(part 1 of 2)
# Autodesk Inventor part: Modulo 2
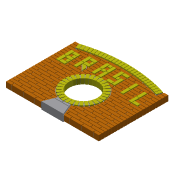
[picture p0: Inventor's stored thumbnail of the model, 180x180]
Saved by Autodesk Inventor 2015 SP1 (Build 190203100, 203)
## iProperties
Created: 2015-04
Part Number: Modulo 2
Material: Generic
Document SubType Name: Modeling
Designer: treina2
Density: 1 g/cm^3
Appearance: Default
Author: treina2
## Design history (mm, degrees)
sketch "Sketch1"
  geometry: L1 (740, 1360)-(740, 1418) reference; L2 (954, 1088)-(954, 1146) reference; L3 (740, 1088)-(740, 1146) reference; L4 (740, 1292)-(740, 1350) reference; L5 (954, 1224)-(954, 1282) reference; L6 (954, 1360)-(954, 1418) reference; L7 (954, 1292)-(954, 1350) reference; L8 (954, 1156)-(954, 1214) reference; L9 (740, 1156)-(740, 1214) reference; L10 (740, 1224)-(740, 1282) reference; L11 (1990, 534)-(1990, 544) reference; L12 (1990, 1350)-(1990, 1360) reference; L13 (740, 262)-(500, 262) reference; L14 (500, 262)-(500, 204) reference; L15 (1875, 136)-(1990, 136) reference; L16 (1990, 136)-(1990, 194) reference; L17 (1990, 194)-(1875, 194) reference; L18 (1875, 194)-(1875, 136) reference; L19 (250, 68)-(490, 68) reference; L20 (490, 68)-(490, 126) reference; L21 (490, 126)-(250, 126) reference; L22 (250, 126)-(250, 68) reference; L23 (750, 68)-(777.045, 68) reference; L24 (1250, 204)-(1490, 204) reference; L25 (1490, 204)-(1490, 262) reference; L26 (1490, 262)-(1250, 262) reference; L27 (1250, 262)-(1250, 204) reference; L28 (1500, 204)-(1740, 204) reference; L29 (1740, 204)-(1740, 262) reference; L30 (1740, 262)-(1500, 262) reference; L31 (1500, 262)-(1500, 204) reference; L32 (125, 136)-(365, 136) reference; L33 (365, 136)-(365, 194) reference; L34 (365, 194)-(125, 194) reference; L35 (125, 194)-(125, 136) reference; L36 (0, 476)-(240, 476) reference; L37 (240, 476)-(240, 534) reference; L38 (240, 534)-(0, 534) reference; L39 (0, 534)-(0, 476) reference; L40 (115, 408)-(0, 408) reference; L41 (0, 408)-(0, 466) reference; L42 (0, 466)-(115, 466) reference; L43 (115, 466)-(115, 408) reference; L44 (1750, 1020)-(1990, 1020) reference; L45 (1990, 1020)-(1990, 1078) reference; L46 (1990, 1078)-(1750, 1078) reference; L47 (1750, 1078)-(1750, 1020) reference; L48 (375, 680)-(570.34, 680) reference; L49 (1500, 884)-(1740, 884) reference; L50 (1740, 884)-(1740, 942) reference; L51 (1740, 942)-(1500, 942) reference; L52 (1500, 942)-(1500, 884) reference; L53 (1750, 884)-(1990, 884) reference; L54 (1990, 884)-(1990, 942) reference; L55 (1990, 942)-(1750, 942) reference; L56 (1750, 942)-(1750, 884) reference; L57 (1250, 1292)-(1422, 1292) reference; L58 (750, 1020)-(764.401, 1020) reference; L59 (250, 1214)-(250, 1156) reference; L60 (250, 1156)-(308, 1156) reference; L61 (750, 1258)-(750, 1418) reference; L62 (750, 1418)-(808, 1418) reference; L63 (808, 1418)-(808, 1258) reference; L64 (808, 1258)-(750, 1258) reference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; C1 r 300 at (995, 663) reference; C2 r 300 at (995, 663) reference; C3 r 300 at (995, 663) reference; C4 r 300 at (995, 663) reference; C5 r 300 at (995, 663) reference; C6 r 300 at (995, 663) reference; A1 r 425 centre (995, 663) between (749.611, 1010) and (683.385, 952) reference; A2 r 2840.721 centre (995, -1354.721) between (490, 1440.752) and (423.896, 1428) reference; A3 r 425 centre (995, 663) between (1411.413, 748) and (1395.22, 806) reference; A4 r 425 centre (995, 663) between (1419.66, 680) and (1413.33, 738) reference; A5 r 425 centre (995, 663) between (863.689, 258.794) and (990, 238.029) reference; A6 r 425 centre (995, 663) between (594.78, 806) and (578.587, 748) reference; A7 r 2840.721 centre (995, -1354.721) between (1615, 1417.516) and (1612.83, 1418) reference; A8 r 425 centre (995, 663) between (903.348, 1078) and (764.401, 1020) reference; A9 r 425 centre (995, 663) between (1376.649, 476) and (1399.949, 534) reference; A10 r 425 centre (995, 663) between (662.735, 398) and (718.783, 340) reference; A11 r 425 centre (995, 663) between (1358.021, 884) and (1315.599, 942) reference; A12 r 425 centre (995, 663) between (1365, 872.105) and (1363.923, 874) reference; A13 r 425 centre (995, 663) between (1225.599, 1020) and (1086.652, 1078) reference; A14 r 425 centre (995, 663) between (1403, 544) and (1415.6, 602) reference; A15 r 425 centre (995, 663) between (1416.929, 612) and (1419.942, 670) reference; A16 r 425 centre (995, 663) between (1161.565, 272) and (1259.076, 330) reference; A17 r 425 centre (995, 663) between (1271.217, 340) and (1327.265, 398) reference; A18 r 425 centre (995, 663) between (1335, 408) and (1365, 453.895) reference; A19 r 425 centre (995, 663) between (574.4, 602) and (587, 544) reference; A20 r 425 centre (995, 663) between (590.051, 534) and (613.351, 476) reference; A21 r 425 centre (995, 663) between (1000, 238.029) and (1126.311, 258.794) reference; A22 r 425 centre (995, 663) between (576.67, 738) and (570.34, 680) reference; A23 r 425 centre (995, 663) between (730.924, 330) and (828.435, 272) reference; A24 r 425 centre (995, 663) between (615, 853.329) and (598.495, 816) reference; A25 r 425 centre (995, 663) between (626.077, 874) and (625, 872.105) reference; A26 r 2840.721 centre (995, -1354.721) between (1831.651, 1360) and (1625, 1415.26) reference; A27 r 425 centre (995, 663) between (674.401, 942) and (631.979, 884) reference; A28 r 2840.721 centre (995, -1354.721) between (365, 1415.26) and (158.349, 1360) reference; A29 r 2840.721 centre (995, -1354.721) between (990, 1485.996) and (750, 1475.415) reference; A30 r 2840.721 centre (995, -1354.721) between (740, 1474.532) and (500, 1442.54) reference; A31 r 2840.721 centre (995, -1354.721) between (377.17, 1418) and (375, 1417.516) reference; A32 r 425 centre (995, 663) between (570.058, 670) and (573.071, 612) reference; A33 r 425 centre (995, 663) between (1391.505, 816) and (1375, 853.329) reference; A34 r 425 centre (995, 663) between (625, 453.895) and (655, 408) reference; A35 r 425 centre (995, 663) between (1306.615, 952) and (1240.389, 1010) reference; A36 r 2840.721 centre (995, -1354.721) between (1490, 1442.54) and (1250, 1474.532) reference; A37 r 2840.721 centre (995, -1354.721) between (1240, 1475.415) and (1000, 1485.996) reference; A38 r 2840.721 centre (995, -1354.721) between (1566.104, 1428) and (1500, 1440.752) reference; 1 further point
  constraints: 2472 end point, 508 horizontal, 481 vertical, 127 point on line, 76 point on circle, 44 centre point, 1 midpoint, 1471 other
extrude "Extrusion1" new body sketch "Sketch1" distance "d0" = 115 (= T_P_L); taper "d1" = 0 deg
extrude "Extrusion2" new body sketch "Sketch1" distance "d2" = 115 (= T_P_L); taper "d3" = 0 deg
extrude "Extrusion3" new body sketch "Sketch1" distance "d4" = 115 (= T_P_L); taper "d5" = 0 deg
extrude "Extrusion4" new body sketch "Sketch1" distance "d6" = 115 (= T_P_L); taper "d7" = 0 deg
extrude "Extrusion6" new body sketch "Sketch1" distance "d10" = 115 (= T_P_L); taper "d11" = 0 deg
extrude "Extrusion7" new body sketch "Sketch1" distance "d12" = 115 (= T_P_L); taper "d13" = 0 deg
extrude "Extrusion8" new body sketch "Sketch1" distance "d14" = 115 (= T_P_L); taper "d15" = 0 deg
extrude "Extrusion9" new body sketch "Sketch1" distance "d16" = 115 (= T_P_L); taper "d17" = 0 deg
extrude "Extrusion10" new body sketch "Sketch1" distance "d18" = 115 (= T_P_L); taper "d19" = 0 deg
extrude "Extrusion11" new body sketch "Sketch1" distance "d20" = 115 (= T_P_L); taper "d21" = 0 deg
extrude "Extrusion12" new body sketch "Sketch1" distance "d22" = 115 (= T_P_L); taper "d23" = 0 deg
extrude "Extrusion13" new body sketch "Sketch1" distance "d24" = 115 (= T_P_L); taper "d25" = 0 deg
extrude "Extrusion14" new body sketch "Sketch1" distance "d26" = 115 (= T_P_L); taper "d27" = 0 deg
extrude "Extrusion15" new body sketch "Sketch1" distance "d28" = 115 (= T_P_L); taper "d29" = 0 deg
pattern_linear "Rectangular Pattern1" dims "d32" = 136 (= 2 x T_P_P + 2 x GAP)
pattern_linear "Rectangular Pattern2" dims "d35" = 136 (= 2 x T_P_P + 2 x GAP)
pattern_linear "Rectangular Pattern3" dims "d38" = 136 (= 2 x T_P_P + 2 x GAP)
pattern_linear "Rectangular Pattern4" dims "d41" = 136 (= 2 x T_P_P + 2 x GAP)
pattern_linear "Rectangular Pattern5" dims "d44" = 136 (= 2 x T_P_P + 2 x GAP)
pattern_linear "Rectangular Pattern6" dims "d47" = 136 (= 2 x T_P_P + 2 x GAP)
extrude "Extrusion16" new body sketch "Sketch1" distance "d48" = 115 (= T_P_L); taper "d49" = 0 deg
extrude "Extrusion17" new body sketch "Sketch1" distance "d50" = 115 (= T_P_L); taper "d51" = 0 deg
extrude "Extrusion18" new body sketch "Sketch1" distance "d52" = 115 (= T_P_L); taper "d53" = 0 deg
pattern_linear "Rectangular Pattern7" dims "d56" = 136 (= 2 x T_P_P + 2 x GAP)
pattern_linear "Rectangular Pattern8" dims "d59" = 136 (= 2 x T_P_P + 2 x GAP)
pattern_linear "Rectangular Pattern9" dims "d62" = 136 (= 2 x T_P_P + 2 x GAP)
pattern_linear "Rectangular Pattern10" dims "d65" = 136 (= 2 x T_P_P + 2 x GAP)
pattern_linear "Rectangular Pattern11" dims "d68" = 136 (= 2 x T_P_P + 2 x GAP)
extrude "Extrusion19" new body sketch "Sketch1" distance "d69" = 115 (= T_P_L); taper "d70" = 0 deg
extrude "Extrusion20" new body sketch "Sketch1" distance "d71" = 115 (= T_P_L); taper "d72" = 0 deg
extrude "Extrusion21" new body sketch "Sketch1" distance "d73" = 115 (= T_P_L); taper "d74" = 0 deg
extrude "Extrusion22" new body sketch "Sketch1" distance "d75" = 115 (= T_P_L); taper "d76" = 0 deg
extrude "Extrusion25" new body sketch "Sketch1" distance "d81" = 115 (= T_P_L); taper "d82" = 0 deg
extrude "Extrusion26" new body sketch "Sketch1" distance "d83" = 115 (= T_P_L); taper "d84" = 0 deg
extrude "Extrusion27" new body sketch "Sketch1" distance "d85" = 115 (= T_P_L); taper "d86" = 0 deg
extrude "Extrusion28" new body sketch "Sketch1" distance "d87" = 115 (= T_P_L); taper "d88" = 0 deg
extrude "Extrusion29" new body sketch "Sketch1" distance "d89" = 115 (= T_P_L); taper "d90" = 0 deg
extrude "Extrusion30" new body sketch "Sketch1" distance "d91" = 115 (= T_P_L); taper "d92" = 0 deg
extrude "Extrusion31" new body sketch "Sketch1" distance "d93" = 115 (= T_P_L); taper "d94" = 0 deg
extrude "Extrusion32" new body sketch "Sketch1" distance "d95" = 115 (= T_P_L); taper "d96" = 0 deg
extrude "Extrusion33" new body sketch "Sketch1" distance "d97" = 115 (= T_P_L); taper "d98" = 0 deg
extrude "Extrusion34" new body sketch "Sketch1" distance "d99" = 115 (= T_P_L); taper "d100" = 0 deg
extrude "Extrusion35" new body sketch "Sketch1" distance "d101" = 115 (= T_P_L); taper "d102" = 0 deg
extrude "Extrusion36" new body sketch "Sketch1" distance "d103" = 115 (= T_P_L); taper "d104" = 0 deg
extrude "Extrusion37" new body sketch "Sketch1" distance "d105" = 115 (= T_P_L); taper "d106" = 0 deg
extrude "Extrusion38" new body sketch "Sketch1" distance "d107" = 115 (= T_P_L); taper "d108" = 0 deg
extrude "Extrusion39" new body sketch "Sketch1" distance "d109" = 115 (= T_P_L); taper "d110" = 0 deg
extrude "Extrusion40" new body sketch "Sketch1" distance "d111" = 115 (= T_P_L); taper "d112" = 0 deg
extrude "Extrusion41" new body sketch "Sketch1" distance "d113" = 115 (= T_P_L); taper "d114" = 0 deg
extrude "Extrusion42" new body sketch "Sketch1" distance "d115" = 115 (= T_P_L); taper "d116" = 0 deg
extrude "Extrusion43" new body sketch "Sketch1" distance "d117" = 115 (= T_P_L); taper "d118" = 0 deg
extrude "Extrusion44" new body sketch "Sketch1" distance "d119" = 115 (= T_P_L); taper "d120" = 0 deg
extrude "Extrusion45" new body sketch "Sketch1" distance "d121" = 115 (= T_P_L); taper "d122" = 0 deg
extrude "Extrusion46" new body sketch "Sketch1" distance "d123" = 115 (= T_P_L); taper "d124" = 0 deg
extrude "Extrusion47" new body sketch "Sketch1" distance "d125" = 115 (= T_P_L); taper "d126" = 0 deg
extrude "Extrusion48" new body sketch "Sketch1" distance "d127" = 115 (= T_P_L); taper "d128" = 0 deg
extrude "Extrusion49" new body sketch "Sketch1" distance "d129" = 115 (= T_P_L); taper "d130" = 0 deg
extrude "Extrusion50" new body sketch "Sketch1" distance "d131" = 115 (= T_P_L); taper "d132" = 0 deg
extrude "Extrusion51" new body sketch "Sketch1" distance "d133" = 115 (= T_P_L); taper "d134" = 0 deg
extrude "Extrusion52" new body sketch "Sketch1" distance "d135" = 115 (= T_P_L); taper "d136" = 0 deg
extrude "Extrusion53" new body sketch "Sketch1" distance "d137" = 115 (= T_P_L); taper "d138" = 0 deg
pattern_linear "Rectangular Pattern12" dims "d141" = 136 (= 2 x T_P_P + 2 x GAP)
pattern_linear "Rectangular Pattern13" dims "d144" = 136 (= 2 x T_P_P + 2 x GAP)
extrude "Extrusion54" new body sketch "Sketch1" distance "d145" = 115 (= T_P_L); taper "d146" = 0 deg
extrude "Extrusion55" new body sketch "Sketch1" distance "d147" = 115 (= T_P_L); taper "d148" = 0 deg
extrude "Extrusion56" new body sketch "Sketch1" distance "d149" = 115 (= T_P_L); taper "d150" = 0 deg
extrude "Extrusion57" new body sketch "Sketch1" distance "d151" = 115 (= T_P_L); taper "d152" = 0 deg
extrude "Extrusion58" new body sketch "Sketch1" distance "d153" = 115 (= T_P_L); taper "d154" = 0 deg
extrude "Extrusion59" new body sketch "Sketch1" distance "d155" = 115 (= T_P_L); taper "d156" = 0 deg
extrude "Extrusion60" new body sketch "Sketch1" distance "d157" = 115 (= T_P_L); taper "d158" = 0 deg
extrude "Extrusion61" new body sketch "Sketch1" distance "d159" = 115 (= T_P_L); taper "d160" = 0 deg
extrude "Extrusion62" new body sketch "Sketch1" distance "d161" = 115 (= T_P_L); taper "d162" = 0 deg
pattern_linear "Rectangular Pattern14" dims "d165" = 68 (= T_P_P + GAP)
extrude "Extrusion63" new body sketch "Sketch1" distance "d166" = 115 (= T_P_L); taper "d167" = 0 deg
extrude "Extrusion64" new body sketch "Sketch1" distance "d168" = 115 (= T_P_L); taper "d169" = 0 deg
extrude "Extrusion65" new body sketch "Sketch1" distance "d170" = 115 (= T_P_L); taper "d171" = 0 deg
extrude "Extrusion66" new body sketch "Sketch1" distance "d172" = 115 (= T_P_L); taper "d173" = 0 deg
extrude "Extrusion67" new body sketch "Sketch1" distance "d174" = 115 (= T_P_L); taper "d175" = 0 deg
extrude "Extrusion68" new body sketch "Sketch1" distance "d176" = 115 (= T_P_L); taper "d177" = 0 deg
extrude "Extrusion69" new body sketch "Sketch1" distance "d178" = 115 (= T_P_L); taper "d179" = 0 deg
extrude "Extrusion70" new body sketch "Sketch1" distance "d180" = 115 (= T_P_L); taper "d181" = 0 deg
pattern_linear "Rectangular Pattern15" dims "d184" = 68 (= T_P_P + GAP)
extrude "Extrusion71" new body sketch "Sketch1" distance "d185" = 115 (= T_P_L); taper "d186" = 0 deg
extrude "Extrusion72" new body sketch "Sketch1" distance "d187" = 115 (= T_P_L); taper "d188" = 0 deg
extrude "Extrusion73" new body sketch "Sketch1" distance "d189" = 115 (= T_P_L); taper "d190" = 0 deg
extrude "Extrusion74" new body sketch "Sketch1" distance "d191" = 115 (= T_P_L); taper "d192" = 0 deg
extrude "Extrusion75" new body sketch "Sketch1" distance "d193" = 115 (= T_P_L); taper "d194" = 0 deg
extrude "Extrusion76" new body sketch "Sketch1" distance "d195" = 115 (= T_P_L); taper "d196" = 0 deg
extrude "Extrusion77" new body sketch "Sketch1" distance "d197" = 115 (= T_P_L); taper "d198" = 0 deg
extrude "Extrusion78" new body sketch "Sketch1" distance "d199" = 115 (= T_P_L); taper "d200" = 0 deg
extrude "Extrusion79" new body sketch "Sketch1" distance "d201" = 115 (= T_P_L); taper "d202" = 0 deg
extrude "Extrusion80" new body sketch "Sketch1" distance "d203" = 115 (= T_P_L); taper "d204" = 0 deg
extrude "Extrusion81" new body sketch "Sketch1" distance "d205" = 115 (= T_P_L); taper "d206" = 0 deg
extrude "Extrusion82" new body sketch "Sketch1" distance "d207" = 115 (= T_P_L); taper "d208" = 0 deg
extrude "Extrusion83" new body sketch "Sketch1" distance "d209" = 115 (= T_P_L); taper "d210" = 0 deg
extrude "Extrusion84" new body sketch "Sketch1" distance "d211" = 115 (= T_P_L); taper "d212" = 0 deg
extrude "Extrusion85" new body sketch "Sketch1" distance "d213" = 115 (= T_P_L); taper "d214" = 0 deg
extrude "Extrusion86" new body sketch "Sketch1" distance "d215" = 115 (= T_P_L); taper "d216" = 0 deg
extrude "Extrusion87" new body sketch "Sketch1" distance "d217" = 115 (= T_P_L); taper "d218" = 0 deg
extrude "Extrusion88" new body sketch "Sketch1" distance "d219" = 115 (= T_P_L); taper "d220" = 0 deg
extrude "Extrusion89" new body sketch "Sketch1" distance "d221" = 115 (= T_P_L); taper "d222" = 0 deg
extrude "Extrusion90" new body sketch "Sketch1" distance "d223" = 115 (= T_P_L); taper "d224" = 0 deg
extrude "Extrusion91" new body sketch "Sketch1" distance "d225" = 115 (= T_P_L); taper "d226" = 0 deg
extrude "Extrusion92" new body sketch "Sketch1" distance "d227" = 115 (= T_P_L); taper "d228" = 0 deg
extrude "Extrusion93" new body sketch "Sketch1" distance "d229" = 115 (= T_P_L); taper "d230" = 0 deg
extrude "Extrusion94" new body sketch "Sketch1" distance "d231" = 115 (= T_P_L); taper "d232" = 0 deg
extrude "Extrusion95" new body sketch "Sketch1" distance "d233" = 115 (= T_P_L); taper "d234" = 0 deg
extrude "Extrusion96" new body sketch "Sketch1" distance "d235" = 115 (= T_P_L); taper "d236" = 0 deg
extrude "Extrusion97" new body sketch "Sketch1" distance "d237" = 115 (= T_P_L); taper "d238" = 0 deg
extrude "Extrusion98" new body sketch "Sketch1" distance "d239" = 115 (= T_P_L); taper "d240" = 0 deg
extrude "Extrusion99" new body sketch "Sketch1" distance "d241" = 115 (= T_P_L); taper "d242" = 0 deg
extrude "Extrusion100" new body sketch "Sketch1" distance "d243" = 115 (= T_P_L); taper "d244" = 0 deg
extrude "Extrusion101" new body sketch "Sketch1" distance "d245" = 115 (= T_P_L); taper "d246" = 0 deg
extrude "Extrusion102" new body sketch "Sketch1" distance "d247" = 115 (= T_P_L); taper "d248" = 0 deg
extrude "Extrusion103" new body sketch "Sketch1" distance "d249" = 115 (= T_P_L); taper "d250" = 0 deg
extrude "Extrusion104" new body sketch "Sketch1" distance "d251" = 115 (= T_P_L); taper "d252" = 0 deg
extrude "Extrusion105" new body sketch "Sketch1" distance "d253" = 115 (= T_P_L); taper "d254" = 0 deg
workplane "Work Plane1"
sketch "Sketch2"
  geometry: L1 (0, 1292)-(0, 1350); L2 (214, 1020)-(214, 1078); L3 (0, 1020)-(0, 1078); L4 (0, 1224)-(0, 1282); L5 (214, 1156)-(214, 1214); L6 (214, 1292)-(214, 1350); L7 (214, 1224)-(214, 1282); L8 (214, 1088)-(214, 1146); L9 (0, 1088)-(0, 1146); L10 (0, 1156)-(0, 1214); L11 (1250, 466)-(1250, 476); L12 (1250, 1282)-(1250, 1292); L13 (0, 194)-(-240, 194); L14 (-240, 194)-(-240, 136); L15 (1135, 68)-(1250, 68); L16 (1250, 68)-(1250, 126); L17 (1250, 126)-(1135, 126); L18 (1135, 126)-(1135, 68); L19 (-490, 0)-(-250, 0); L20 (-250, 0)-(-250, 58); L21 (-250, 58)-(-490, 58); L22 (-490, 58)-(-490, 0); L23 (10, 0)-(37.045, 0); L24 (510, 136)-(750, 136); L25 (750, 136)-(750, 194); L26 (750, 194)-(510, 194); L27 (510, 194)-(510, 136); L28 (760, 136)-(1000, 136); L29 (1000, 136)-(1000, 194); L30 (1000, 194)-(760, 194); L31 (760, 194)-(760, 136); L32 (-615, 68)-(-375, 68); L33 (-375, 68)-(-375, 126); L34 (-375, 126)-(-615, 126); L35 (-615, 126)-(-615, 68); L36 (-740, 408)-(-500, 408); L37 (-500, 408)-(-500, 466); L38 (-500, 466)-(-740, 466); L39 (-740, 466)-(-740, 408); L40 (-625, 340)-(-740, 340); L41 (-740, 340)-(-740, 398); L42 (-740, 398)-(-625, 398); L43 (-625, 398)-(-625, 340); L44 (1010, 952)-(1250, 952); L45 (1250, 952)-(1250, 1010); L46 (1250, 1010)-(1010, 1010); L47 (1010, 1010)-(1010, 952); L48 (-365, 612)-(-169.66, 612); L49 (760, 816)-(1000, 816); L50 (1000, 816)-(1000, 874); L51 (1000, 874)-(760, 874); L52 (760, 874)-(760, 816); L53 (1010, 816)-(1250, 816); L54 (1250, 816)-(1250, 874); L55 (1250, 874)-(1010, 874); L56 (1010, 874)-(1010, 816); L57 (510, 1224)-(682, 1224); L58 (10, 952)-(24.401, 952); L59 (-490, 1146)-(-490, 1088); L60 (-490, 1088)-(-432, 1088); L61 (10, 1190)-(10, 1350); L62 (10, 1350)-(68, 1350); L63 (68, 1350)-(68, 1190); L64 (68, 1190)-(10, 1190)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; C1 r 300 at (255, 595); C2 r 300 at (255, 595); C3 r 300 at (255, 595); C4 r 300 at (255, 595); C5 r 300 at (255, 595); C6 r 300 at (255, 595); A1 r 425 centre (255, 595) between (9.611, 942) and (-56.615, 884); A2 r 2840.721 centre (255, -1422.721) between (-250, 1372.752) and (-316.104, 1360); A3 r 425 centre (255, 595) between (671.413, 680) and (655.22, 738); A4 r 425 centre (255, 595) between (679.66, 612) and (673.33, 670); A5 r 425 centre (255, 595) between (123.689, 190.794) and (250, 170.029); A6 r 425 centre (255, 595) between (-145.22, 738) and (-161.413, 680); A7 r 2840.721 centre (255, -1422.721) between (875, 1349.516) and (872.83, 1350); A8 r 425 centre (255, 595) between (163.348, 1010) and (24.401, 952); A9 r 425 centre (255, 595) between (636.649, 408) and (659.949, 466); A10 r 425 centre (255, 595) between (-77.265, 330) and (-21.217, 272); A11 r 425 centre (255, 595) between (618.021, 816) and (575.599, 874); A12 r 425 centre (255, 595) between (625, 804.105) and (623.923, 806); A13 r 425 centre (255, 595) between (485.599, 952) and (346.652, 1010); A14 r 425 centre (255, 595) between (663, 476) and (675.6, 534); A15 r 425 centre (255, 595) between (676.929, 544) and (679.942, 602); A16 r 425 centre (255, 595) between (421.565, 204) and (519.076, 262); A17 r 425 centre (255, 595) between (531.217, 272) and (587.265, 330); A18 r 425 centre (255, 595) between (595, 340) and (625, 385.895); A19 r 425 centre (255, 595) between (-165.6, 534) and (-153, 476); A20 r 425 centre (255, 595) between (-149.949, 466) and (-126.649, 408); A21 r 425 centre (255, 595) between (260, 170.029) and (386.311, 190.794); A22 r 425 centre (255, 595) between (-163.33, 670) and (-169.66, 612); A23 r 425 centre (255, 595) between (-9.076, 262) and (88.435, 204); A24 r 425 centre (255, 595) between (-125, 785.329) and (-141.505, 748); A25 r 425 centre (255, 595) between (-113.923, 806) and (-115, 804.105); A26 r 2840.721 centre (255, -1422.721) between (1091.651, 1292) and (885, 1347.26); A27 r 425 centre (255, 595) between (-65.599, 874) and (-108.021, 816); A28 r 2840.721 centre (255, -1422.721) between (-375, 1347.26) and (-581.651, 1292); A29 r 2840.721 centre (255, -1422.721) between (250, 1417.996) and (10, 1407.415); A30 r 2840.721 centre (255, -1422.721) between (0, 1406.532) and (-240, 1374.54); A31 r 2840.721 centre (255, -1422.721) between (-362.83, 1350) and (-365, 1349.516); A32 r 425 centre (255, 595) between (-169.942, 602) and (-166.929, 544); A33 r 425 centre (255, 595) between (651.505, 748) and (635, 785.329); A34 r 425 centre (255, 595) between (-115, 385.895) and (-85, 340); A35 r 425 centre (255, 595) between (566.615, 884) and (500.389, 942); A36 r 2840.721 centre (255, -1422.721) between (750, 1374.54) and (510, 1406.532); A37 r 2840.721 centre (255, -1422.721) between (500, 1407.415) and (260, 1417.996); A38 r 2840.721 centre (255, -1422.721) between (826.104, 1360) and (760, 1372.752); 2 further points
  constraints: 2472 end point, 127 point on line, 76 point on circle, 44 centre point, 1 midpoint
extrude "Extrusion106" new body sketch "Sketch2" distance "d255" = 15; taper "d257" = 0 deg; dims "d256" = 140 (derived), "d258" = 0
extrude "Extrusion107" new body sketch "Sketch2" distance "d259" = 15; taper "d261" = 0 deg; dims "d260" = 140 (derived), "d262" = 0
extrude "Extrusion108" new body sketch "Sketch2" distance "d263" = 15; taper "d265" = 0 deg; dims "d264" = 140 (derived), "d266" = 0
workplane "Work Plane2"
sketch "Sketch3"
  geometry: L1 (906.204, 951.021)-(963.017, 962.697) reference; L2 (963.017, 962.697)-(939.867, 1075.343) reference; L3 (939.867, 1075.343)-(883.055, 1063.667) reference; L4 (883.055, 1063.667)-(906.204, 951.021) reference; L5 (939.867, 1075.343)-(883.055, 1063.667); L6 (906.204, 951.021)-(883.055, 1063.667); L7 (963.017, 962.697)-(906.204, 951.021); L8 (939.867, 1075.343)-(963.017, 962.697); L9 (903.343, 950.124)-(850.043, 927.251); L10 (850.043, 927.251)-(804.693, 1032.931); L11 (857.992, 1055.804)-(903.343, 950.124); L12 (857.992, 1055.804)-(804.693, 1032.931); L13 (847.422, 925.796)-(799.817, 892.662); L14 (799.817, 892.662)-(734.122, 987.05); L15 (781.726, 1020.184)-(847.422, 925.796); L16 (781.726, 1020.184)-(734.122, 987.05); L17 (797.542, 890.709)-(757.582, 848.671); L18 (757.582, 848.671)-(674.231, 927.902); L19 (714.191, 969.94)-(797.542, 890.709); L20 (714.191, 969.94)-(674.231, 927.902); L21 (755.747, 846.3)-(725.067, 797.079); L22 (725.067, 797.079)-(627.473, 857.909); L23 (658.153, 907.131)-(755.747, 846.3); L24 (658.153, 907.131)-(627.473, 857.909); L25 (723.746, 794.386)-(703.603, 739.997); L26 (703.603, 739.997)-(595.761, 779.937); L27 (615.905, 834.326)-(723.746, 794.386); L28 (615.905, 834.326)-(595.761, 779.937); L29 (702.851, 737.094)-(694.068, 679.763); L30 (694.068, 679.763)-(580.394, 697.177); L31 (589.177, 754.508)-(702.851, 737.094); L32 (589.177, 754.508)-(580.394, 697.177); L33 (693.916, 676.768)-(696.854, 618.842); L34 (696.854, 618.842)-(582.001, 613.018); L35 (579.064, 670.943)-(693.916, 676.768); L36 (579.064, 670.943)-(582.001, 613.018); L37 (697.308, 615.878)-(711.846, 559.73); L38 (711.846, 559.73)-(600.517, 530.905); L39 (585.979, 587.053)-(697.308, 615.878); L40 (585.979, 587.053)-(600.517, 530.905); L41 (712.887, 556.918)-(738.43, 504.845); L42 (738.43, 504.845)-(635.183, 454.2); L43 (609.64, 506.273)-(712.887, 556.918); L44 (609.64, 506.273)-(635.183, 454.2); L45 (740.016, 502.301)-(775.518, 456.436); L46 (775.518, 456.436)-(684.579, 386.044); L47 (649.077, 431.909)-(740.016, 502.301); L48 (649.077, 431.909)-(684.579, 386.044); L49 (777.584, 454.262)-(821.592, 416.483); L50 (821.592, 416.483)-(746.684, 329.226); L51 (702.676, 367.005)-(777.584, 454.262); L52 (702.676, 367.005)-(746.684, 329.226); L53 (824.053, 414.77)-(874.765, 386.622); L54 (874.765, 386.622)-(818.956, 286.072); L55 (768.244, 314.22)-(824.053, 414.77); L56 (768.244, 314.22)-(818.956, 286.072); L57 (877.521, 385.44)-(932.861, 368.077); L58 (932.861, 368.077)-(898.434, 258.351); L59 (843.094, 275.714)-(877.521, 385.44); L60 (843.094, 275.714)-(898.434, 258.351); L61 (935.798, 367.473)-(993.501, 361.605); L62 (993.501, 361.605)-(981.866, 247.195); L63 (924.164, 253.063)-(935.798, 367.473); L64 (924.164, 253.063)-(981.866, 247.195)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; C1 r 156.317 at (995, 663); A1 r 425 centre (995, 663) between (1000, 238.029) and (1126.311, 258.794) reference; A2 r 425 centre (995, 663) between (863.689, 258.794) and (990, 238.029) reference; 2 further points
  constraints: 248 end point, 3 collinear, 1 centre point, 1 coincident, 249 other
  dimensions: "d270" = 360 deg dimension on point (995, 663) L1.end (derived)
  node "Project Cut Edges1"
extrude "Extrusion109" new body sketch "Sketch3" distance "d272" = 115 (derived); taper "d273" = 0 deg
workplane "Work Plane3"
sketch "Sketch4"
  geometry: L1 (308, 1146)-(193, 1146) reference; L2 (308, 1088)-(308, 1146) reference; L3 (193, 1088)-(308, 1088) reference; L4 (193, 1146)-(193, 1112) reference; L5 (193, 1122)-(193, 1088) reference; L6 (183, 1282)-(183, 1122) reference; L7 (183, 1282)-(125, 1282) reference; L8 (125, 1122)-(125, 1282) reference; L9 (183, 1122)-(125, 1122) reference; L10 (125, 1112)-(183, 1112) reference; L11 (125, 952)-(125, 1112) reference; L12 (183, 1112)-(183, 952) reference; L13 (183, 952)-(125, 952) reference; L14 (308, 1020)-(250, 1020) reference; L15 (250, 1078)-(250, 1020) reference; L16 (308, 1078)-(250, 1078) reference; L17 (308, 1078)-(308, 1020) reference; L18 (308, 952)-(308, 1010) reference; L19 (308, 1010)-(193, 1010) reference; L20 (193, 952)-(308, 952) reference; L21 (193, 1010)-(193, 952) reference; L22 (250, 1156)-(308, 1156) reference; L23 (308, 1214)-(308, 1156) reference; L24 (250, 1214)-(308, 1214) reference; L25 (250, 1214)-(250, 1156) reference; L26 (240, 1224)-(308, 1224) reference; L27 (308, 1224)-(308, 1282) reference; L28 (308, 1282)-(193, 1282) reference; L29 (193, 1282)-(193, 1224) reference; L30 (193, 1224)-(308, 1224) reference; L31 (490, 1292)-(490, 1350) reference; L32 (432, 1350)-(490, 1350) reference; L33 (432, 1282)-(432, 1350) reference; L34 (432, 1190)-(432, 1350) reference; L35 (490, 1350)-(490, 1190) reference; L36 (490, 1190)-(432, 1190) reference; L37 (432, 1180)-(490, 1180) reference; L38 (490, 1180)-(490, 1020) reference; L39 (432, 1020)-(432, 1180) reference; L40 (490, 1020)-(432, 1020) reference; L41 (500, 1135)-(547, 1088) reference; L42 (500, 1146)-(500, 1135) reference; L43 (571.024, 1146)-(500, 1146) reference; L44 (615, 1102.024)-(571.024, 1146) reference; L45 (615, 1020)-(615, 1088) reference; L46 (547, 1088)-(615, 1020) reference; L47 (615, 1088)-(615, 1102.024) reference; L48 (615, 1156)-(615, 1214) reference; L49 (615, 1214)-(500, 1214) reference; L50 (500, 1156)-(615, 1156) reference; L51 (500, 1190)-(500, 1156) reference; L52 (500, 1214)-(500, 1180) reference; L53 (567.5, 1224)-(615, 1224) reference; L54 (567.5, 1224)-(567.5, 1282) reference; L55 (615, 1282)-(615, 1224) reference; L56 (615, 1282)-(567.5, 1282) reference; L57 (500, 1292)-(615, 1292) reference; L58 (615, 1292)-(615, 1350) reference; L59 (500, 1350)-(500, 1292) reference; L60 (615, 1350)-(500, 1350) reference; L61 (750, 1418)-(808, 1418) reference; L62 (750, 1258)-(750, 1418) reference; L63 (808, 1258)-(750, 1258) reference; L64 (808, 1418)-(808, 1258) reference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; 1 further point
extrude "Extrusion110" new body sketch "Sketch4" distance "d278" = 115 (derived); taper "d279" = 0 deg
extrude "Extrusion111" new body sketch "Sketch4" distance "d280" = 115 (derived); taper "d281" = 0 deg
extrude "Extrusion112" new body sketch "Sketch4" distance "d282" = 115 (derived); taper "d283" = 0 deg
extrude "Extrusion113" new body sketch "Sketch4" distance "d284" = 115 (derived); taper "d285" = 0 deg
pattern_linear "Rectangular Pattern16" dims "d288" = 136 (derived)
pattern_linear "Rectangular Pattern17" dims "d291" = 136 (derived)
extrude "Extrusion114" new body sketch "Sketch4" distance "d292" = 115 (derived); taper "d293" = 0 deg
extrude "Extrusion115" new body sketch "Sketch4" distance "d294" = 115 (derived); taper "d295" = 0 deg
extrude "Extrusion116" new body sketch "Sketch4" distance "d296" = 115 (derived); taper "d297" = 0 deg
extrude "Extrusion117" new body sketch "Sketch4" distance "d298" = 115 (derived); taper "d299" = 0 deg
extrude "Extrusion118" new body sketch "Sketch4" distance "d300" = 115 (derived); taper "d301" = 0 deg
extrude "Extrusion119" new body sketch "Sketch4" distance "d302" = 115 (derived); taper "d303" = 0 deg
extrude "Extrusion120" new body sketch "Sketch4" distance "d304" = 115 (derived); taper "d305" = 0 deg
extrude "Extrusion121" new body sketch "Sketch4" distance "d306" = 115 (derived); taper "d307" = 0 deg
extrude "Extrusion122" new body sketch "Sketch4" distance "d308" = 115 (derived); taper "d309" = 0 deg
extrude "Extrusion123" new body sketch "Sketch4" distance "d310" = 115 (derived); taper "d311" = 0 deg
extrude "Extrusion124" new body sketch "Sketch4" distance "d312" = 115 (derived); taper "d313" = 0 deg
extrude "Extrusion125" new body sketch "Sketch4" distance "d314" = 115 (derived); taper "d315" = 0 deg
extrude "Extrusion126" new body sketch "Sketch4" distance "d316" = 115 (derived); taper "d317" = 0 deg
extrude "Extrusion127" new body sketch "Sketch4" distance "d318" = 115 (derived); taper "d319" = 0 deg
extrude "Extrusion128" new body sketch "Sketch4" distance "d320" = 115 (derived); taper "d321" = 0 deg
extrude "Extrusion129" new body sketch "Sketch4" distance "d322" = 115 (derived); taper "d323" = 0 deg
extrude "Extrusion130" new body sketch "Sketch4" distance "d324" = 115 (derived); taper "d325" = 0 deg
extrude "Extrusion131" new body sketch "Sketch4" distance "d326" = 115 (derived); taper "d327" = 0 deg
extrude "Extrusion132" new body sketch "Sketch4" distance "d328" = 115 (derived); taper "d329" = 0 deg
extrude "Extrusion133" new body sketch "Sketch4" distance "d330" = 115 (derived); taper "d331" = 0 deg
extrude "Extrusion134" new body sketch "Sketch4" distance "d332" = 115 (derived); taper "d333" = 0 deg
extrude "Extrusion135" new body sketch "Sketch4" distance "d334" = 115 (derived); taper "d335" = 0 deg
sketch "Sketch5"
  geometry: L1 (740, 1360)-(740, 1418); L2 (954, 1088)-(954, 1146); L3 (740, 1088)-(740, 1146); L4 (740, 1292)-(740, 1350); L5 (954, 1224)-(954, 1282); L6 (954, 1360)-(954, 1418); L7 (954, 1292)-(954, 1350); L8 (954, 1156)-(954, 1214); L9 (740, 1156)-(740, 1214); L10 (740, 1224)-(740, 1282); L11 (1990, 534)-(1990, 544); L12 (1990, 1350)-(1990, 1360); L13 (740, 262)-(500, 262); L14 (500, 262)-(500, 204); L15 (1875, 136)-(1990, 136); L16 (1990, 136)-(1990, 194); L17 (1990, 194)-(1875, 194); L18 (1875, 194)-(1875, 136); L19 (250, 68)-(490, 68); L20 (490, 68)-(490, 126); L21 (490, 126)-(250, 126); L22 (250, 126)-(250, 68); L23 (750, 68)-(777.045, 68); L24 (1250, 204)-(1490, 204); L25 (1490, 204)-(1490, 262); L26 (1490, 262)-(1250, 262); L27 (1250, 262)-(1250, 204); L28 (1500, 204)-(1740, 204); L29 (1740, 204)-(1740, 262); L30 (1740, 262)-(1500, 262); L31 (1500, 262)-(1500, 204); L32 (125, 136)-(365, 136); L33 (365, 136)-(365, 194); L34 (365, 194)-(125, 194); L35 (125, 194)-(125, 136); L36 (0, 476)-(240, 476); L37 (240, 476)-(240, 534); L38 (240, 534)-(0, 534); L39 (0, 534)-(0, 476); L40 (115, 408)-(0, 408); L41 (0, 408)-(0, 466); L42 (0, 466)-(115, 466); L43 (115, 466)-(115, 408); L44 (1750, 1020)-(1990, 1020); L45 (1990, 1020)-(1990, 1078); L46 (1990, 1078)-(1750, 1078); L47 (1750, 1078)-(1750, 1020); L48 (375, 680)-(570.34, 680); L49 (1500, 884)-(1740, 884); L50 (1740, 884)-(1740, 942); L51 (1740, 942)-(1500, 942); L52 (1500, 942)-(1500, 884); L53 (1750, 884)-(1990, 884); L54 (1990, 884)-(1990, 942); L55 (1990, 942)-(1750, 942); L56 (1750, 942)-(1750, 884); L57 (1250, 1292)-(1422, 1292); L58 (750, 1020)-(764.401, 1020); L59 (250, 1214)-(250, 1156); L60 (250, 1156)-(308, 1156); L61 (750, 1258)-(750, 1418); L62 (750, 1418)-(808, 1418); L63 (808, 1418)-(808, 1258); L64 (808, 1258)-(750, 1258)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; C1 r 300 at (995, 663); C2 r 300 at (995, 663); C3 r 300 at (995, 663); C4 r 300 at (995, 663); C5 r 300 at (995, 663); C6 r 300 at (995, 663); A1 r 425 centre (995, 663) between (749.611, 1010) and (683.385, 952); A2 r 2840.721 centre (995, -1354.721) between (490, 1440.752) and (423.896, 1428); A3 r 425 centre (995, 663) between (1411.413, 748) and (1395.22, 806); A4 r 425 centre (995, 663) between (1419.66, 680) and (1413.33, 738); A5 r 425 centre (995, 663) between (863.689, 258.794) and (990, 238.029); A6 r 425 centre (995, 663) between (594.78, 806) and (578.587, 748); A7 r 2840.721 centre (995, -1354.721) between (1615, 1417.516) and (1612.83, 1418); A8 r 425 centre (995, 663) between (903.348, 1078) and (764.401, 1020); A9 r 425 centre (995, 663) between (1376.649, 476) and (1399.949, 534); A10 r 425 centre (995, 663) between (662.735, 398) and (718.783, 340); A11 r 425 centre (995, 663) between (1358.021, 884) and (1315.599, 942); A12 r 425 centre (995, 663) between (1365, 872.105) and (1363.923, 874); A13 r 425 centre (995, 663) between (1225.599, 1020) and (1086.652, 1078); A14 r 425 centre (995, 663) between (1403, 544) and (1415.6, 602); A15 r 425 centre (995, 663) between (1416.929, 612) and (1419.942, 670); A16 r 425 centre (995, 663) between (1161.565, 272) and (1259.076, 330); A17 r 425 centre (995, 663) between (1271.217, 340) and (1327.265, 398); A18 r 425 centre (995, 663) between (1335, 408) and (1365, 453.895); A19 r 425 centre (995, 663) between (574.4, 602) and (587, 544); A20 r 425 centre (995, 663) between (590.051, 534) and (613.351, 476); A21 r 425 centre (995, 663) between (1000, 238.029) and (1126.311, 258.794); A22 r 425 centre (995, 663) between (576.67, 738) and (570.34, 680); A23 r 425 centre (995, 663) between (730.924, 330) and (828.435, 272); A24 r 425 centre (995, 663) between (615, 853.329) and (598.495, 816); A25 r 425 centre (995, 663) between (626.077, 874) and (625, 872.105); A26 r 2840.721 centre (995, -1354.721) between (1831.651, 1360) and (1625, 1415.26); A27 r 425 centre (995, 663) between (674.401, 942) and (631.979, 884); A28 r 2840.721 centre (995, -1354.721) between (365, 1415.26) and (158.349, 1360); A29 r 2840.721 centre (995, -1354.721) between (990, 1485.996) and (750, 1475.415); A30 r 2840.721 centre (995, -1354.721) between (740, 1474.532) and (500, 1442.54); A31 r 2840.721 centre (995, -1354.721) between (377.17, 1418) and (375, 1417.516); A32 r 425 centre (995, 663) between (570.058, 670) and (573.071, 612); A33 r 425 centre (995, 663) between (1391.505, 816) and (1375, 853.329); A34 r 425 centre (995, 663) between (625, 453.895) and (655, 408); A35 r 425 centre (995, 663) between (1306.615, 952) and (1240.389, 1010); A36 r 2840.721 centre (995, -1354.721) between (1490, 1442.54) and (1250, 1474.532); A37 r 2840.721 centre (995, -1354.721) between (1240, 1475.415) and (1000, 1485.996); A38 r 2840.721 centre (995, -1354.721) between (1566.104, 1428) and (1500, 1440.752); 3 further points
  constraints: 2472 end point, 127 point on line, 76 point on circle, 44 centre point, 1 midpoint
extrude "Extrusion136" new body sketch "Sketch5" distance "d336" = 115 (derived); taper "d337" = 0 deg
extrude "Extrusion137" new body sketch "Sketch5" distance "d338" = 115 (derived); taper "d339" = 0 deg
extrude "Extrusion138" new body sketch "Sketch5" distance "d340" = 115 (derived); taper "d341" = 0 deg
extrude "Extrusion139" new body sketch "Sketch5" distance "d342" = 115 (derived); taper "d343" = 0 deg
extrude "Extrusion140" new body sketch "Sketch5" distance "d344" = 115 (derived); taper "d345" = 0 deg
extrude "Extrusion141" new body sketch "Sketch5" distance "d346" = 115 (derived); taper "d347" = 0 deg
extrude "Extrusion142" new body sketch "Sketch5" distance "d348" = 115 (derived); taper "d349" = 0 deg
extrude "Extrusion143" new body sketch "Sketch5" distance "d350" = 115 (derived); taper "d351" = 0 deg
extrude "Extrusion144" new body sketch "Sketch5" distance "d352" = 115 (derived); taper "d353" = 0 deg
extrude "Extrusion145" new body sketch "Sketch5" distance "d354" = 115 (derived); taper "d355" = 0 deg
extrude "Extrusion146" new body sketch "Sketch5" distance "d356" = 115 (derived); taper "d357" = 0 deg
extrude "Extrusion147" new body sketch "Sketch5" distance "d358" = 115 (derived); taper "d359" = 0 deg
extrude "Extrusion148" new body sketch "Sketch5" distance "d360" = 115 (derived); taper "d361" = 0 deg
extrude "Extrusion149" new body sketch "Sketch5" distance "d362" = 115 (derived); taper "d363" = 0 deg
extrude "Extrusion150" new body sketch "Sketch5" distance "d364" = 115 (derived); taper "d365" = 0 deg
extrude "Extrusion151" new body sketch "Sketch5" distance "d366" = 115 (derived); taper "d367" = 0 deg
extrude "Extrusion152" new body sketch "Sketch5" distance "d368" = 115 (derived); taper "d369" = 0 deg
extrude "Extrusion153" new body sketch "Sketch5" distance "d370" = 115 (derived); taper "d371" = 0 deg
extrude "Extrusion154" new body sketch "Sketch5" distance "d372" = 115 (derived); taper "d373" = 0 deg
extrude "Extrusion155" new body sketch "Sketch5" distance "d374" = 115 (derived); taper "d375" = 0 deg
extrude "Extrusion156" new body sketch "Sketch5" distance "d376" = 115 (derived); taper "d377" = 0 deg
extrude "Extrusion157" new body sketch "Sketch5" distance "d378" = 115 (derived); taper "d379" = 0 deg
extrude "Extrusion158" new body sketch "Sketch5" distance "d380" = 115 (derived); taper "d381" = 0 deg
extrude "Extrusion159" new body sketch "Sketch5" distance "d382" = 115 (derived); taper "d383" = 0 deg
extrude "Extrusion160" new body sketch "Sketch5" distance "d384" = 115 (derived); taper "d385" = 0 deg
extrude "Extrusion161" new body sketch "Sketch5" distance "d386" = 115 (derived); taper "d387" = 0 deg
extrude "Extrusion162" new body sketch "Sketch5" distance "d388" = 115 (derived); taper "d389" = 0 deg
workplane "Work Plane4"
workplane "Work Plane5"
sketch "Sketch6"
  geometry: L1 (-412.081, 126)-(-489.238, -68) reference; L2 (-101.896, 136)-(-123.689, 190.794) reference; L3 (-20.762, -68)-(-97.919, 126) reference; L4 (-489.238, -68)-(-20.762, -68) reference; L5 (-386.311, 190.794)-(-408.104, 136) reference; L6 (-20.762, -68)-(-123.689, 190.794); L7 (-97.919, 126)-(-20.762, -68) reference; L8 (-20.762, -68)-(-489.238, -68); L9 (-489.238, -68)-(-386.311, 190.794); L10 (-395.798, 194)-(-418.865, 136) reference; A1 r 425 centre (-255, 595) between (-386.311, 190.794) and (-260, 170.029) reference; A2 r 425 centre (-255, 595) between (-250, 170.029) and (-123.689, 190.794) reference; A3 r 425 centre (-255, 595) between (-386.311, 190.794) and (-123.689, 190.794); 1 further point
  constraints: 6 end point, 2 collinear, 2 point on circle, 1 centre point, 1 parallel
extrude "Extrusion163" new body sketch "Sketch6" distance "d392" = 135; taper "d393" = 0 deg
workplane "Work Plane6"
sketch "Sketch7"
  geometry: L1 (-11.979, 117.796)-(-0.303, 60.983) reference; L2 (0, 58)-(0, 0) reference; L3 (0, 29)-(-300, 29); L4 (-6.141, 89.39)-(-300, 29); L5 (115, 0)-(115, 58) reference; C1 r 310 at (-300, 29); C2 r 405 at (-300, 29); 1 further point
  constraints: 4 end point, 2 centre point, 2 coincident, 2 midpoint, 1 horizontal, 1 perpendicular
  dimensions: "d395" = 10 distance edge to line of C1 L1; "d396" = 10 distance edge to line of C2 L5 (derived)
extrude "Extrusion164" join sketch "Sketch7" distance "d397" = 95; taper "d398" = 0 deg
workplane "Work Plane7"
sketch "Sketch8"
  geometry: L1 (-165.38, 874)-(-146.792, 816) reference; L2 (-10, 738)-(-250, 738) reference; L3 (1740, 874)-(1655.38, 874) reference; L4 (1633.588, 806)-(1625, 779.204) reference; L5 (1740, 738)-(1500, 738) reference; L6 (1740, 874)-(1740, -612); L7 (1740, -612)-(-250, -612); L8 (-250, -612)-(-250, 874); L9 (-250, 874)-(-165.38, 874); L10 (-165.38, 874)-(-124.847, 747.523); L11 (1740, 874)-(1655.38, 874); L12 (1655.38, 874)-(1614.847, 747.523); L13 (1655.38, 874)-(1636.792, 816) reference; C1 r 405 at (745, 51) reference; C2 r 436.685 at (745, 51); A1 r 2840.721 centre (745, -1966.721) between (115, 803.26) and (-91.651, 748) reference; A2 r 2840.721 centre (745, -1966.721) between (1581.651, 748) and (1375, 803.26) reference; A3 r 2767.321 centre (745, -1890.066) between (1611.795, 738) and (-121.795, 738); A4 r 2777.321 centre (745, -1890.066) between (1614.847, 747.523) and (-124.847, 747.523) reference; A5 r 2881.211 centre (745, -1890.066) between (1646.554, 846.46) and (-156.554, 846.46)
  constraints: 14 end point, 6 point on circle, 4 centre point, 4 point on line, 3 perpendicular, 2 collinear, 1 coincident, 1 horizontal, 1 vertical, 1 other
  dimensions: "d400" = 10 radial gap between concentric circles of A3 A4
extrude "Extrusion165" join sketch "Sketch8" distance "d401" = 95; taper "d402" = 0 deg
sketch "Sketch9"
  geometry: C1 r 405 at (-745, 51) reference; C2 r 435 at (-745, 51); A1 r 425 centre (-745, 51) between (-1169.942, 58) and (-1166.929, 0) reference; 1 further point
  constraints: 1 centre point, 1 coincident
  dimensions: "d405" = 10 radial gap between concentric circles of C2 A1
extrude "Extrusion166" cut sketch "Sketch9" stored distance "d403" = 215; taper "d404" = 0 deg
extrude "Extrusion167" join sketch "Sketch8" distance "d406" = 80; taper "d408" = 0 deg; dims "d407" = 15, "d409" = 0
sketch "Sketch10"
  geometry: L1 (-1490, 330)-(-1250, 330) reference; L2 (-1422, 330)-(-1422, 679.817); L3 (-1422, 679.817)-(-1500.197, 679.817); L4 (-1500.197, 679.817)-(-1500.197, 407.908); L5 (-1490, 670)-(-1490, 510) reference; L6 (-1500.197, 407.908)-(-1625, 407.908); L7 (-1625, 407.908)-(-1625, 330); L8 (-1625, 330)-(-1422, 330); L9 (-1365, 398)-(-1125, 398) reference; L10 (-1125, 748)-(-1365, 748) reference; L11 (-1172, 398)-(-1250, 398); L12 (-1250, 398)-(-1250, 748); L13 (-1250, 748)-(-1172, 748); L14 (-1172, 748)-(-1172, 398); L15 (-750, 816)-(-990, 816) reference; L16 (-1000, 466.079)-(-797, 466.079); L17 (-797, 466.079)-(-797, 816); L18 (-797, 816)-(-1000, 816); L19 (-1000, 816)-(-1000, 466.079); L20 (-490, 816)-(-704, 816); L21 (-704, 816)-(-704, 466.079); L22 (-704, 466.079)-(-490, 466.079); L23 (-490, 466.079)-(-490, 816); L24 (-125, 748)-(-365, 748) reference; L25 (-171.226, 748)-(-375, 748); L26 (-375, 748)-(-375, 398); L27 (-375, 398)-(-171.226, 398); L28 (-171.226, 398)-(-171.226, 748); L29 (-240, 330)-(0, 330) reference; L30 (135, 679.817)-(-68.82, 679.817); L31 (-68.82, 679.817)-(-68.82, 330); L32 (-68.82, 330)-(135, 330); L33 (135, 330)-(135, 679.817); 1 further point
  constraints: 52 end point, 11 parallel, 9 perpendicular, 8 point on line, 5 horizontal, 1 vertical
extrude "Extrusion168" cut sketch "Sketch10" distance "d410" = 1; taper "d411" = 0 deg
node "Direct Edit1"
combine "Combine1"
node "M2.1"
pattern_circular "Circular Pattern1" dims "d275" = 360 deg
node "M2.2"
node "M2.3"
node "M2.4"
node "M2.5"
node "M2.7"
node "M2.8"
node "M2.9"
node "M2.10"
node "M2.11"
node "M2.12"
node "M2.13"
node "M2.14"
node "M2.15"
feature "Pattern of M2.15:1"
node "M2.16"
feature "Pattern of M2.15:2"
node "M2.17"
feature "Pattern of M2.15:3"
node "M2.18"
feature "Pattern of M2.15:4"
node "M2.19"
feature "Pattern of M2.15:5"
node "M2.20"
feature "Pattern of M2.15:6"
node "M2.21"
feature "Pattern of M2.15:7"
node "M2.22"
feature "Pattern of M2.15:8"
node "M2.23"
feature "Pattern of M2.15:9"
node "M2.24"
feature "Pattern of M2.15:10"
node "M2.25"
feature "Pattern of M2.15:11"
node "M2.26"
feature "Pattern of M2.15:12"
node "M2.27"
feature "Pattern of M2.15:13"
node "M2.28"
feature "Pattern of M2.15:14"
node "M2.29"
feature "Pattern of M2.15:15"
node "M2.30"
feature "Pattern of M2.15:16"
node "M2.31"
feature "Pattern of M2.15:17"
node "M2.32"
feature "Pattern of M2.15:18"
node "M2.33"
feature "Pattern of M2.15:19"
node "M2.34"
feature "Pattern of M2.15:20"
node "M2.35"
feature "Pattern of M2.15:21"
node "M2.36"
feature "Pattern of M2.15:22"
node "M2.37"
feature "Pattern of M2.15:23"
node "M2.38"
feature "Pattern of M2.15:24"
node "M2.39"
feature "Pattern of M2.15:25"
node "M2.40"
feature "Pattern of M2.15:26"
node "M2.41"
feature "Pattern of M2.15:27"
node "M2.42"
feature "Pattern of M2.15:28"
node "M2.43"
feature "Pattern of M2.15:29"
node "M2.44"
feature "Pattern of M2.15:30"
body "Solid45"
feature "Pattern of M2.15:31"
body "Solid46"
feature "Pattern of M2.15:32"
body "Solid47"
feature "Pattern of M2.15:33"
body "Solid48"
feature "Pattern of M2.15:34"
body "Solid49"
body "Solid50"
body "Solid51"
body "Solid52"
feature "Pattern of M2.15:35"
body "Solid53"
feature "Pattern of M2.15:36"
body "Solid54"
feature "Pattern of M2.15:37"
body "Solid55"
feature "Pattern of M2.15:38"
body "Solid56"
feature "Pattern of M2.15:39"
body "Solid57"
feature "Pattern of M2.15:40"
body "Solid58"
feature "Pattern of M2.15:41"
body "Solid59"
feature "Pattern of M2.15:42"
body "Solid60"
feature "Pattern of M2.15:43"
body "Solid61"
feature "Pattern of M2.15:44"
body "Solid62"
feature "Pattern of M2.15:45"
body "Solid63"
feature "Pattern of M2.15:46"
body "Solid64"
feature "Pattern of M2.15:47"
body "Solid65"
feature "Pattern of M2.15:48"
body "Solid66"
feature "Pattern of M2.15:49"
body "Solid67"
feature "Pattern of M2.15:50"
body "Solid68"
feature "Pattern of M2.15:51"
body "Solid69"
feature "Pattern of M2.15:52"
body "Solid70"
feature "Pattern of M2.15:53"
body "Solid71"
feature "Pattern of M2.15:54"
body "Solid72"
feature "Pattern of M2.15:55"
body "Solid73"
feature "Pattern of M2.15:56"
body "Solid74"
feature "Pattern of M2.15:57"
body "Solid75"
feature "Pattern of M2.15:58"
body "Solid76"
feature "Pattern of M2.15:59"
body "Solid77"
feature "Pattern of M2.15:60"
node "M2.78"
feature "Pattern of M2.15:61"
node "M2.79"
feature "Pattern of M2.15:62"
node "M2.80"
body "Solid81"
body "Solid82"
body "Solid83"
body "Solid84"
body "Solid87"
body "Solid88"
body "Solid89"
body "Solid90"
body "Solid91"
body "Solid92"
body "Solid93"
body "Solid94"
body "Solid95"
body "Solid96"
body "Solid97"
body "Solid98"
body "Solid99"
body "Solid100"
body "Solid101"
body "Solid102"
body "Solid103"
body "Solid104"
body "Solid105"
body "Solid106"
body "Solid107"
body "Solid108"
body "Solid109"
body "Solid110"
body "Solid111"
body "Solid112"
body "Solid113"
body "Solid114"
body "Solid115"
feature "Pattern of M2.15:63"
body "Solid116"
feature "Pattern of M2.15:64"
body "Solid117"
body "Solid118"
body "Solid119"
body "Solid120"
body "Solid121"
body "Solid122"
body "Solid123"
body "Solid124"
body "Solid125"
body "Solid126"
body "Solid127"
body "Solid128"
body "Solid129"
body "Solid130"
body "Solid131"
body "Solid132"
body "Solid133"
body "Solid134"
feature "Pattern of M2.15:65"
body "Solid135"
feature "Pattern of M2.15:66"
body "Solid136"
feature "Pattern of M2.15:67"
body "Solid137"
feature "Pattern of M2.15:68"
body "Solid138"
feature "Pattern of M2.15:69"
body "Solid139"
feature "Pattern of M2.15:70"
body "Solid140"
feature "Pattern of M2.15:71"
body "Solid141"
feature "Pattern of M2.15:72"
body "Solid142"
feature "Pattern of M2.15:73"
body "Solid143"
body "Solid144"
body "Solid145"
body "Solid146"
body "Solid147"
body "Solid148"
body "Solid149"
body "Solid150"
body "Solid151"
body "Solid152"
body "Solid153"
body "Solid154"
body "Solid155"
body "Solid156"
body "Solid157"
body "Solid158"
body "Solid159"
body "Solid160"
body "Solid161"
body "Solid162"
body "Solid163"
body "Solid164"
body "Solid165"
body "Solid166"
body "Solid167"
body "Solid168"
body "Solid169"
body "Solid170"
body "Solid171"
body "Solid172"
body "Solid173"
body "Solid174"
body "Solid175"
body "Solid176"
body "Solid177"
body "Solid178"
body "Solid179"
body "Solid180"
body "Solid181"
body "Solid182"
feature "Pattern of M2.44:74"
body "Solid183"
feature "Pattern of M2.44:75"
body "Solid184"
feature "Pattern of M2.44:76"
body "Solid185"
feature "Pattern of M2.44:77"
body "Solid186"
feature "Pattern of M2.44:78"
body "Solid187"
feature "Pattern of M2.44:79"
body "Solid188"
feature "Pattern of M2.44:80"
body "Solid189"
feature "Pattern of M2.44:81"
